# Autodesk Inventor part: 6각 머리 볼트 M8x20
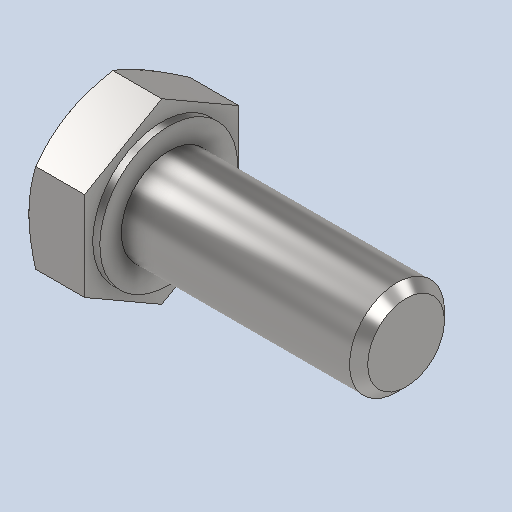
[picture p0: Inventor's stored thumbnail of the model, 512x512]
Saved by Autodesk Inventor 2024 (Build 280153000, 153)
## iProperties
Created: 2025-11
Part Number: 6각 머리 볼트 M8x20
Material: 강철, 연강
Description: 6각 머리 볼트 및 6각 머리 나사
Document SubType Name: Modeling
Designer: Edu07
Density: 7.85 g/cm^3
Appearance: 기본값
Author: jhkim
Sending System: Autodesk Inventor 2026
Preprocessor: ST-DEVELOPER v20.1
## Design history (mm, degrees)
node "6각 머리 볼트 M8x201"
node "솔리드1"
body "Solid1"
